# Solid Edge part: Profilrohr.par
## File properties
Username: ahadarics
Dokumentum tartalom típus: 0
Author: ahadarics
Last saved by: ahadarics
Revision: 84
Sűrűség: 0,000 kg/m^3
Pontosság: 0,990
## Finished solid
Body 1: solid body, 6 faces, 6 edges, 0 vertices.
  Faces by surface: cone 2, cylinder 2, plane 2
  Edges by curve: circle 6
Bounding box of the edges (mm): 17.270 x 17.270 x 282.000, from (-8.635, -8.635, -261) to (8.635, 8.635, 21).
Cylindrical faces by radius (mm): R8 x1, R8.635 x1
Conical faces (half-angle, radius in mm at the cone's reference point): 15 deg R8.067 x2
Planar faces by outward normal: +z 1, -z 1
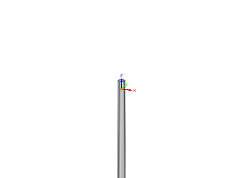
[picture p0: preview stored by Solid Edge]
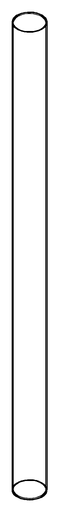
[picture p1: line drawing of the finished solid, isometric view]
